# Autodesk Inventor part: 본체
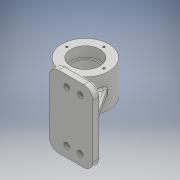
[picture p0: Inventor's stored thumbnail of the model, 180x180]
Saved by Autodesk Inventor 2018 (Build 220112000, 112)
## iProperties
Created: 2023-08
Part Number: 본체
Material: 일반
Document SubType Name: Modeling
Designer: home
Density: 1 g/cm^3
Appearance: 기본값
Mass: 285.547 g
Surface Area: 534.467 cm^2
Volume: 285.547 cm^3
Author: home
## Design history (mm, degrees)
sketch "스케치1"
  geometry: C1 r 38 at (0, 0); 1 further point
  constraints: 1 centre point, 1 coincident
  dimensions: "d0" = 76 diameter of C1
extrude "돌출1" new body sketch "스케치1" stored distance "d1" = 54; taper "d2" = 0 deg
node "작업 평면1"
sketch "스케치2"
  geometry: L1 (0, 0)-(-12, 0); L2 (-12, 0)-(-12, -58); L3 (-12, -58)-(-82, -58); L4 (-82, -58)-(-82, 58); L5 (-82, 58)-(-12, 58); L6 (-12, 58)-(-12, -58)
  constraints: 12 end point, 2 horizontal, 2 parallel, 2 perpendicular
  dimensions: "d4" = 12 distance of L1.start L1.end; "d5" = 58 distance of L1.end L2.end; "d6" = 70 distance of L4.end L5.end; "d7" = 116 distance of L3.end L4.end
extrude "돌출2" join sketch "스케치2" distance "d8" = 12; taper "d9" = 0 deg
sketch "스케치3"
  geometry: L1 (116, 0)-(0, 0) reference; L2 (116, 0)-(116, 12) reference; L3 (0, 12)-(116, 12) reference; L4 (0, 0)-(0, 12) reference; L5 (0, 12)-(22, 12); L6 (22, 12)-(41.062, 41.353); L7 (116, 12)-(94, 12); L8 (94, 12)-(74.938, 41.353); L9 (94, 12)-(129, 12); L10 (41.062, 41.353)-(74.938, 41.353); L11 (22, 12)-(94, 12); 1 further point
  constraints: 14 end point, 2 point on line, 1 collinear, 1 equal length, 1 horizontal
  dimensions: "d10" = 22 distance of L3.start L5.end; "d11" = 35 distance of L5.end L6.end; "d12" = 123 deg angle of L6 L5; "d13" = 22 distance of L2.end L7.end; "d14" = 35 distance of L7.end L8.end; "d15" = 123 deg angle of L9 L8
extrude "돌출3" join sketch "스케치3" distance "d16" = 8; taper "d17" = 0 deg
sketch "스케치4"
  geometry: L1 (12, -70)-(82, -70) reference; L2 (12, -70)-(12, -58) reference; L3 (82, -58)-(12, -58) reference; L4 (82, -70)-(82, -58) reference; L5 (12, -58)-(74, -58); L6 (74, -58)-(36.334, 0); L7 (74, -58)-(143.157, -58); 1 further point
  constraints: 6 end point, 1 equal length, 1 horizontal, 1 point on line
  dimensions: "d18" = 62 distance of L2.end L5.end; "d19" = 123 deg angle of L7 L6; "d87" = 61.15707 distance from line of L7.end L4
feature "리브1" sketch "스케치4" dims "d20" = 1, "d21" = 12, "d22" = 0, "d23" = 0, "d24" = 1, "d25" = 1
sketch "스케치5" dims "d36" = 10
  geometry: L1 (0, 0)-(40, 0); L2 (40, 0)-(40, -41); L3 (40, -41)-(62, -41); L4 (40, -41)-(62, -41); L5 (40, -51)-(62, -51); L6 (62, -31)-(40, -31); L7 (62, 51)-(40, 51); L8 (40, 31)-(62, 31); A1 r 10 centre (40, -41) between (40, -31) and (40, -51); A2 r 10 centre (62, -41) between (62, -51) and (62, -31); A3 r 10 centre (62, 41) between (62, 31) and (62, 51); A4 r 10 centre (40, 41) between (40, 51) and (40, 31); 1 further point
  constraints: 18 end point, 8 point on circle, 4 centre point, 4 tangent, 3 horizontal, 1 midpoint, 1 parallel, 1 perpendicular, 1 vertical, 10 other
  dimensions: "d26" = 40 distance of L1.start L1.end; "d27" = 41 distance of L1.end L2.end; "d28" = 22 distance of L2.end L3.end; "d30" = 20 diameter of A2; "d33" = 82 distance of L6.start L7.start
extrude "돌출4" join sketch "스케치5" distance "d38" = 3; taper "d39" = 0 deg
sketch "스케치6"
  geometry: L1 (62, 51)-(40, 51) reference; L2 (40, 31)-(62, 31) reference; L3 (40, -51)-(62, -51) reference; L4 (62, -31)-(40, -31) reference; A1 r 10 centre (40, 41) between (40, 51) and (40, 31) reference; A2 r 10 centre (62, 41) between (62, 31) and (62, 51) reference; A3 r 10 centre (62, -41) between (62, -51) and (62, -31) reference; A4 r 10 centre (40, -41) between (40, -31) and (40, -51) reference; 5 further points
  constraints: 4 coincident
hole "구멍1" sketch "스케치6" at (62, 41), (40, 41), (62, -41), (40, -41) diameter "d40" = 9; stored, may be unused: countersink angle "d44" = 90 deg, drill point angle "d46" = 118 deg; dims "d41" = 6, "d42" = 4, "d43" = 2, "d45" = 8
sketch "스케치7"
  geometry: C1 r 23.5 at (0, 0); 1 further point
  constraints: 1 centre point, 1 coincident
  dimensions: "d47" = 47 diameter of C1
extrude "돌출5" cut sketch "스케치7" distance "d48" = 17; taper "d49" = 0 deg
sketch "스케치8"
  geometry: C1 r 20.5 at (0, 0); 1 further point
  constraints: 1 centre point, 1 coincident
  dimensions: "d50" = 41 diameter of C1
extrude "돌출6" cut sketch "스케치8" stored distance "d51" = 17; taper "d52" = 0 deg
sketch "스케치9" dims "d53" = 60
  geometry: L1 (0, 0)-(0, 30); 4 further points
  constraints: 2 end point, 1 coincident, 1 vertical, 1 vertical alignment, 7 other
  dimensions: "d56" = 360 deg dimension on point (0, 0) L1.end (derived)
hole "구멍2" sketch "스케치9" at (0, 30), (-30, 0), (0, -30), (30, 0) diameter "d58" = 3.242; stored, may be unused: countersink angle "d62" = 90 deg, drill point angle "d64" = 118 deg; dims "d59" = 8, "d60" = 4, "d61" = 2, "d63" = 10
node "작업 평면2"
sketch "스케치10"
  geometry: C1 r 8 at (0, 0); 1 further point
  constraints: 1 centre point, 1 coincident
  dimensions: "d66" = 16 diameter of C1
extrude "돌출7" join sketch "스케치10" stored distance "d67" = 17; taper "d68" = 0 deg
hole "구멍3" diameter "d71" = 5.188; stored, may be unused: countersink angle "d75" = 90 deg, drill point angle "d77" = 118 deg; dims "d72" = 22, "d73" = 7, "d74" = 4, "d76" = 26, "d78" = 10, "d79" = 10
fillet "모깎기1" dims "d80" = 1, "d81" = 3
fillet "모깎기2" dims "d82" = 3, "d86" = 15
sketch "스케치11"
  geometry: L1 (37.266, 30)-(78.734, 30) reference; L2 (23.629, 9)-(37.266, 30) reference; L3 (15, 9)-(23.629, 9) reference; L4 (101, 0)-(15, 0) reference; L5 (92.371, 9)-(101, 9) reference; L6 (78.734, 30)-(92.371, 9) reference; L7 (58, 0)-(58, 19); L8 (15, 0)-(15, 9) reference; L9 (101, 9)-(101, 0) reference; 2 further points
  constraints: 2 end point, 1 coincident, 1 midpoint, 1 vertical, 1 other
  dimensions: "d83" = 19 distance of L7.start L7.end
feature "엠보싱1" sketch "스케치11" dims "d10" = 22, "d11" = 35, "d12" = 123 deg, "d13" = 22, "d14" = 35, "d15" = 123 deg, "d84" = 0.5, "d85" = 0
node "솔리드1"
mirror "미러1"
mirror "미러2"
node "투영된 루프1"
node "투영된 루프2"
node "투영된 루프3"
node "투영된 루프4"
node "투영된 루프5"
other parameters: "d65" = -111
